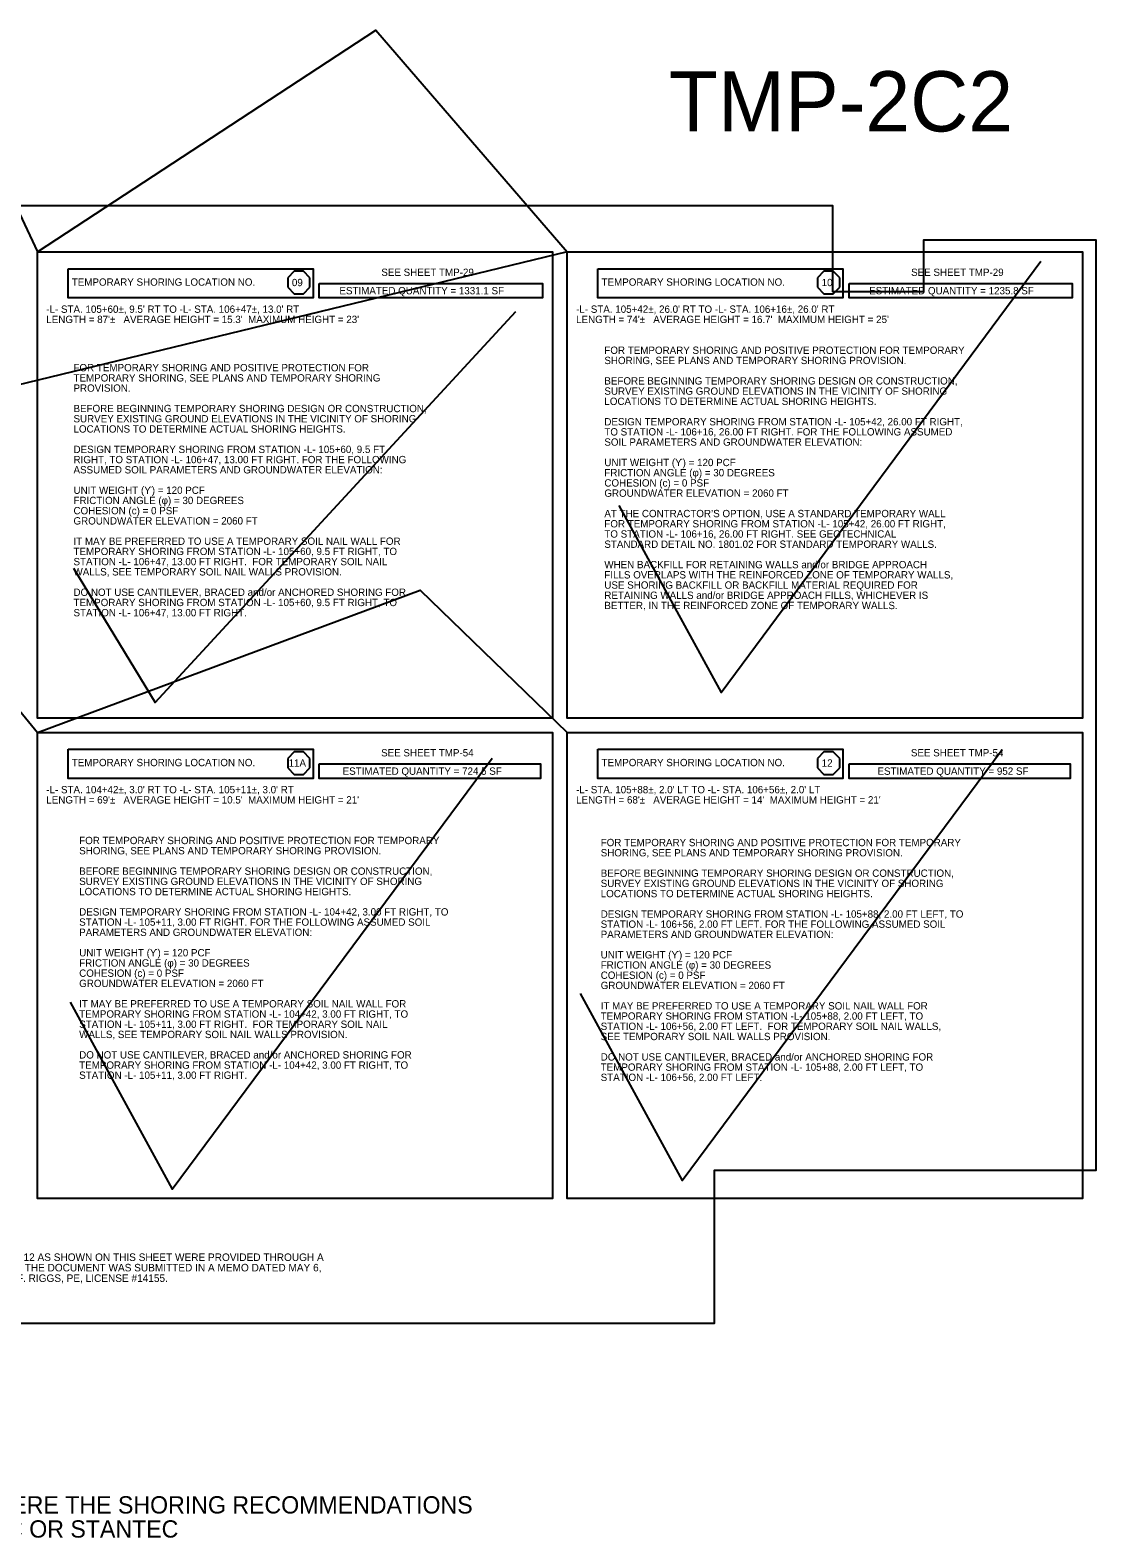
# Model space of a CAD drawing. Extents: x 2487012 to 2497594, y 369516 to 371986.
# Drawn here: x 2494835 to 2495826, y 370043 to 371445 of the extents above; entities that cross this region are included whole.
import ezdxf

# ---------------------------------------------------------------- set-up
doc = ezdxf.new("R2010")
doc.units = 0
for name, color, linetype in [('Scratch_Level_2', 7, 'Continuous'), ('Scratch_Level_6', 7, 'Continuous'), ('TC LABEL TEMP SHORING', 7, 'Continuous'), ('TC SHEET BORDER LINE THIN', 7, 'Continuous'), ('TC SHEET LAYOUT SHAPE', 7, 'Continuous'), ('TC SHEET TEXT', 7, 'Continuous')]:
    doc.layers.add(name, color=color, linetype=linetype)

msp = doc.modelspace()

# ---------------------------------------------------------------- linework, layer by layer
at = {"layer": 'Scratch_Level_2'}
for points in [[(2495382.7, 371003.4), (2495477.7, 370829.5), (2495775.3, 371230.4)], [(2494875.2, 370945), (2494951.2, 370819.9), (2495286.6, 371183.7)], [(2494872, 370541.3), (2494967, 370367.5), (2495264.6, 370768.3)], [(2495346.7, 370549.4), (2495441.6, 370375.6), (2495739.3, 370776.4)]]:
    msp.add_lwpolyline(points, dxfattribs=at)
at = {"layer": 'Scratch_Level_6'}
msp.add_lwpolyline([(2494336.4, 371282.3), (2494348.7, 371239.1), (2494750.3, 371433.4), (2494841.6, 371239.1), (2495156.4, 371445.4), (2495334.5, 371239.1), (2494163.1, 370955.2), (2494348.7, 370792.3), (2494709, 370953.9), (2494841.6, 370792.3), (2495197.6, 370924.6), (2495334.5, 370792.3)], dxfattribs=at)
at = {"layer": 'TC LABEL TEMP SHORING'}
for p, q in [((2495080.6, 371221.2), (2495074.5, 371215)), ((2495089.2, 371221.2), (2495080.6, 371221.2)), ((2495095.2, 371215), (2495089.2, 371221.2)), ((2495573.4, 371221.2), (2495567.4, 371215)), ((2495582.1, 371221.2), (2495573.4, 371221.2)), ((2495588.1, 371215), (2495582.1, 371221.2)), ((2495074.5, 371215), (2495074.5, 371206.3)), ((2495074.5, 371206.3), (2495080.6, 371200.1)), ((2495089.2, 371200.1), (2495095.2, 371206.3)), ((2495095.2, 371206.3), (2495095.2, 371215)), ((2495567.4, 371215), (2495567.4, 371206.3)), ((2495567.4, 371206.3), (2495573.4, 371200.1)), ((2495582.1, 371200.1), (2495588.1, 371206.3)), ((2495588.1, 371206.3), (2495588.1, 371215)), ((2495080.6, 371200.1), (2495089.2, 371200.1)), ((2495573.4, 371200.1), (2495582.1, 371200.1)), ((2495080.6, 370774.3), (2495074.5, 370768.1)), ((2495074.5, 370768.1), (2495074.5, 370759.4)), ((2495089.2, 370774.3), (2495080.6, 370774.3)), ((2495095.2, 370768.1), (2495089.2, 370774.3)), ((2495095.2, 370759.4), (2495095.2, 370768.1)), ((2495573.4, 370774.3), (2495567.4, 370768.1)), ((2495567.4, 370768.1), (2495567.4, 370759.4)), ((2495582.1, 370774.3), (2495573.4, 370774.3)), ((2495588.1, 370768.1), (2495582.1, 370774.3)), ((2495588.1, 370759.4), (2495588.1, 370768.1)), ((2495074.5, 370759.4), (2495080.6, 370753.2)), ((2495089.2, 370753.2), (2495095.2, 370759.4)), ((2495567.4, 370759.4), (2495573.4, 370753.2)), ((2495582.1, 370753.2), (2495588.1, 370759.4)), ((2495080.6, 370753.2), (2495089.2, 370753.2)), ((2495573.4, 370753.2), (2495582.1, 370753.2))]:
    msp.add_line(p, q, dxfattribs=at)
at = {"layer": 'TC SHEET BORDER LINE THIN'}
for points in [[(2494841.6, 371239.1), (2495321, 371239.1), (2495321, 370805.5), (2494841.6, 370805.5)], [(2495334.5, 371239.1), (2495813.9, 371239.1), (2495813.9, 370805.5), (2495334.5, 370805.5)], [(2494870.1, 371223.5), (2495098.1, 371223.5), (2495098.1, 371196.3), (2494870.1, 371196.3)], [(2495363, 371223.5), (2495591, 371223.5), (2495591, 371196.3), (2495363, 371196.3)], [(2495103.9, 371209.9), (2495311.4, 371209.9), (2495311.4, 371196.3), (2495103.9, 371196.3)], [(2495596.8, 371209.9), (2495804.3, 371209.9), (2495804.3, 371196.3), (2495596.8, 371196.3)], [(2494841.6, 370792.3), (2495321, 370792.3), (2495321, 370358.6), (2494841.6, 370358.6)], [(2495334.5, 370792.3), (2495813.9, 370792.3), (2495813.9, 370358.6), (2495334.5, 370358.6)], [(2494870.1, 370776.7), (2495098.1, 370776.7), (2495098.1, 370749.4), (2494870.1, 370749.4)], [(2495363, 370776.7), (2495591, 370776.7), (2495591, 370749.4), (2495363, 370749.4)], [(2495103.9, 370763), (2495309.7, 370763), (2495309.7, 370749.4), (2495103.9, 370749.4)], [(2495596.8, 370763), (2495802.6, 370763), (2495802.6, 370749.4), (2495596.8, 370749.4)]]:
    msp.add_lwpolyline(points, close=True, dxfattribs=at)
at = {"layer": 'TC SHEET LAYOUT SHAPE'}
msp.add_lwpolyline([(2494336.4, 370690.8), (2494336.4, 371000.2), (2494336.4, 371272.3), (2494346.4, 371282.3), (2494789.4, 371282.3), (2495260.4, 371282.3), (2495581.4, 371282.3), (2495581.4, 371202.3), (2495666.4, 371202.3), (2495666.4, 371250.3), (2495826.4, 371250.3), (2495826.4, 370915.3), (2495826.4, 370636.1), (2495826.4, 370384.8), (2495471.4, 370384.8), (2495471.4, 370242.3), (2495098.2, 370242.3), (2494928.7, 370242.3), (2494576, 370242.3), (2494336.4, 370242.3)], close=True, dxfattribs=at)

# ---------------------------------------------------------------- texts
at = {"layer": 'Scratch_Level_6'}
for s, p in [('MODIFY THIS DEPENDING ON WHERE THE SHORING RECOMMENDATIONS ', (2494464.6, 370065.7)), ('WERE SENT EITHER NCDOT WZTC OR STANTEC', (2494464.6, 370043.3))]:
    msp.add_text(s, height=16.094, dxfattribs=at).set_placement(p)
at = {"layer": 'TC LABEL TEMP SHORING'}
for s, p in [('09', (2495078.4, 371207.3)), ('10', (2495571.3, 371207.3)), ('11A', (2495075.3, 370760.4)), ('12', (2495571.3, 370760.4))]:
    msp.add_text(s, height=6.81, dxfattribs=at).set_placement(p)
at = {"layer": 'TC SHEET BORDER LINE THIN'}
for s, height, p in [('FOR TEMPORARY SHORING AND POSITIVE PROTECTION FOR TEMPORARY ', 6.814, (2495369.1, 371144.3)), ('FOR TEMPORARY SHORING AND POSITIVE PROTECTION FOR', 6.814, (2494875.2, 371128.1)), ('SHORING, SEE PLANS AND TEMPORARY SHORING PROVISION.', 6.814, (2495369.1, 371134.8)), ('TEMPORARY SHORING, SEE PLANS AND TEMPORARY SHORING', 6.814, (2494875.2, 371118.6)), ('BEFORE BEGINNING TEMPORARY SHORING DESIGN OR CONSTRUCTION, ', 6.814, (2495369.1, 371115.8)), ('PROVISION.', 6.81, (2494875.2, 371109.1)), ('SURVEY EXISTING GROUND ELEVATIONS IN THE VICINITY OF SHORING ', 6.814, (2495369.1, 371106.3)), ('BEFORE BEGINNING TEMPORARY SHORING DESIGN OR CONSTRUCTION,', 6.814, (2494875.2, 371090.1)), ('LOCATIONS TO DETERMINE ACTUAL SHORING HEIGHTS.', 6.814, (2495369.1, 371096.8)), ('SURVEY EXISTING GROUND ELEVATIONS IN THE VICINITY OF SHORING', 6.814, (2494875.2, 371080.6)), ('LOCATIONS TO DETERMINE ACTUAL SHORING HEIGHTS.', 6.814, (2494875.2, 371071.1)), ('DESIGN TEMPORARY SHORING FROM STATION -L- 105+42, 26.00 FT RIGHT, ', 6.814, (2495369.1, 371077.8)), ('TO STATION -L- 106+16, 26.00 FT RIGHT. FOR THE FOLLOWING ASSUMED ', 6.814, (2495369.1, 371068.4)), ('SOIL PARAMETERS AND GROUNDWATER ELEVATION:', 6.814, (2495369.1, 371058.9)), ('DESIGN TEMPORARY SHORING FROM STATION -L- 105+60, 9.5 FT', 6.814, (2494875.2, 371052.1)), ('RIGHT, TO STATION -L- 106+47, 13.00 FT RIGHT. FOR THE FOLLOWING', 6.814, (2494875.2, 371042.6)), ('ASSUMED SOIL PARAMETERS AND GROUNDWATER ELEVATION:', 6.814, (2494875.2, 371033.1)), ('UNIT WEIGHT (ϒ) = 120 PCF', 6.814, (2495369.1, 371039.9)), ('FRICTION ANGLE (φ) = 30 DEGREES', 6.814, (2495369.1, 371030.4)), ('UNIT WEIGHT (ϒ) = 120 PCF', 6.814, (2494875.2, 371014.1)), ('COHESION (c) = 0 PSF', 6.814, (2495369.1, 371020.9)), ('FRICTION ANGLE (φ) = 30 DEGREES', 6.814, (2494875.2, 371004.6)), ('GROUNDWATER ELEVATION = 2060 FT', 6.814, (2495369.1, 371011.4)), ('COHESION (c) = 0 PSF', 6.814, (2494875.2, 370995.1)), ('GROUNDWATER ELEVATION = 2060 FT', 6.814, (2494875.2, 370985.6)), ('AT THE CONTRACTOR’S OPTION, USE A STANDARD TEMPORARY WALL', 6.814, (2495369.1, 370992.4)), ('TO STATION -L- 106+16, 26.00 FT RIGHT. SEE GEOTECHNICAL', 6.814, (2495369.1, 370973.4)), ('FOR TEMPORARY SHORING FROM STATION -L- 105+42, 26.00 FT RIGHT,', 6.814, (2495369.1, 370982.9)), ('TEMPORARY SHORING FROM STATION -L- 105+60, 9.5 FT RIGHT, TO', 6.814, (2494875.2, 370957.2)), ('IT MAY BE PREFERRED TO USE A TEMPORARY SOIL NAIL WALL FOR', 6.814, (2494875.2, 370966.7)), ('STANDARD DETAIL NO. 1801.02 FOR STANDARD TEMPORARY WALLS.', 6.814, (2495369.1, 370963.9)), ('STATION -L- 106+47, 13.00 FT RIGHT.  FOR TEMPORARY SOIL NAIL', 6.814, (2494875.2, 370947.7)), ('WHEN BACKFILL FOR RETAINING WALLS and/or BRIDGE APPROACH', 6.814, (2495369.1, 370944.9)), ('WALLS, SEE TEMPORARY SOIL NAIL WALLS PROVISION.', 6.814, (2494875.2, 370938.2)), ('FILLS OVERLAPS WITH THE REINFORCED ZONE OF TEMPORARY WALLS,', 6.814, (2495369.1, 370935.4)), ('DO NOT USE CANTILEVER, BRACED and/or ANCHORED SHORING FOR', 6.814, (2494875.2, 370919.2)), ('USE SHORING BACKFILL OR BACKFILL MATERIAL REQUIRED FOR', 6.814, (2495369.1, 370925.9)), ('RETAINING WALLS and/or BRIDGE APPROACH FILLS, WHICHEVER IS', 6.814, (2495369.1, 370916.4)), ('TEMPORARY SHORING FROM STATION -L- 105+60, 9.5 FT RIGHT, TO', 6.814, (2494875.2, 370909.7)), ('BETTER, IN THE REINFORCED ZONE OF TEMPORARY WALLS.', 6.814, (2495369.1, 370906.9)), ('STATION -L- 106+47, 13.00 FT RIGHT.', 6.814, (2494875.2, 370900.2)), ('SHORING, SEE PLANS AND TEMPORARY SHORING PROVISION.', 6.814, (2494880.5, 370678.8)), ('FOR TEMPORARY SHORING AND POSITIVE PROTECTION FOR TEMPORARY ', 6.814, (2494880.5, 370688.3)), ('SHORING, SEE PLANS AND TEMPORARY SHORING PROVISION.', 6.814, (2495365.7, 370676.9)), ('FOR TEMPORARY SHORING AND POSITIVE PROTECTION FOR TEMPORARY ', 6.814, (2495365.7, 370686.4)), ('SURVEY EXISTING GROUND ELEVATIONS IN THE VICINITY OF SHORING ', 6.814, (2494880.5, 370650.3)), ('BEFORE BEGINNING TEMPORARY SHORING DESIGN OR CONSTRUCTION, ', 6.814, (2494880.5, 370659.8)), ('BEFORE BEGINNING TEMPORARY SHORING DESIGN OR CONSTRUCTION, ', 6.814, (2495365.7, 370657.9)), ('LOCATIONS TO DETERMINE ACTUAL SHORING HEIGHTS.', 6.814, (2494880.5, 370640.8)), ('SURVEY EXISTING GROUND ELEVATIONS IN THE VICINITY OF SHORING ', 6.814, (2495365.7, 370648.4)), ('LOCATIONS TO DETERMINE ACTUAL SHORING HEIGHTS.', 6.814, (2495365.7, 370638.9)), ('DESIGN TEMPORARY SHORING FROM STATION -L- 104+42, 3.00 FT RIGHT, TO ', 6.814, (2494880.5, 370621.9)), ('STATION -L- 105+11, 3.00 FT RIGHT. FOR THE FOLLOWING ASSUMED SOIL ', 6.814, (2494880.5, 370612.4)), ('STATION -L- 106+56, 2.00 FT LEFT. FOR THE FOLLOWING ASSUMED SOIL ', 6.814, (2495365.7, 370610.5)), ('DESIGN TEMPORARY SHORING FROM STATION -L- 105+88, 2.00 FT LEFT, TO ', 6.814, (2495365.7, 370619.9)), ('PARAMETERS AND GROUNDWATER ELEVATION:', 6.814, (2494880.5, 370602.9)), ('PARAMETERS AND GROUNDWATER ELEVATION:', 6.814, (2495365.7, 370601)), ('UNIT WEIGHT (ϒ) = 120 PCF', 6.814, (2494880.5, 370583.9)), ('UNIT WEIGHT (ϒ) = 120 PCF', 6.814, (2495365.7, 370582)), ('COHESION (c) = 0 PSF', 6.814, (2494880.5, 370564.9)), ('FRICTION ANGLE (φ) = 30 DEGREES', 6.814, (2494880.5, 370574.4)), ('FRICTION ANGLE (φ) = 30 DEGREES', 6.814, (2495365.7, 370572.5)), ('GROUNDWATER ELEVATION = 2060 FT', 6.814, (2494880.5, 370555.4)), ('COHESION (c) = 0 PSF', 6.814, (2495365.7, 370563)), ('GROUNDWATER ELEVATION = 2060 FT', 6.814, (2495365.7, 370553.5)), ('IT MAY BE PREFERRED TO USE A TEMPORARY SOIL NAIL WALL FOR', 6.814, (2494880.5, 370536.4)), ('TEMPORARY SHORING FROM STATION -L- 104+42, 3.00 FT RIGHT, TO', 6.814, (2494880.5, 370526.9)), ('TEMPORARY SHORING FROM STATION -L- 105+88, 2.00 FT LEFT, TO', 6.814, (2495365.7, 370525)), ('IT MAY BE PREFERRED TO USE A TEMPORARY SOIL NAIL WALL FOR', 6.814, (2495365.7, 370534.5)), ('STATION -L- 105+11, 3.00 FT RIGHT.  FOR TEMPORARY SOIL NAIL', 6.814, (2494880.5, 370517.4)), ('STATION -L- 106+56, 2.00 FT LEFT.  FOR TEMPORARY SOIL NAIL WALLS,', 6.814, (2495365.7, 370515.5)), ('WALLS, SEE TEMPORARY SOIL NAIL WALLS PROVISION.', 6.814, (2494880.5, 370507.9)), ('SEE TEMPORARY SOIL NAIL WALLS PROVISION.', 6.814, (2495365.7, 370506)), ('DO NOT USE CANTILEVER, BRACED and/or ANCHORED SHORING FOR', 6.814, (2494880.5, 370488.9)), ('DO NOT USE CANTILEVER, BRACED and/or ANCHORED SHORING FOR', 6.814, (2495365.7, 370487)), ('TEMPORARY SHORING FROM STATION -L- 104+42, 3.00 FT RIGHT, TO', 6.814, (2494880.5, 370479.4)), ('STATION -L- 105+11, 3.00 FT RIGHT.', 6.814, (2494880.5, 370470)), ('TEMPORARY SHORING FROM STATION -L- 105+88, 2.00 FT LEFT, TO', 6.814, (2495365.7, 370477.5)), ('STATION -L- 106+56, 2.00 FT LEFT.', 6.814, (2495365.7, 370468))]:
    msp.add_text(s, height=height, dxfattribs=at).set_placement(p)
at = {"layer": 'TC SHEET LAYOUT SHAPE'}
msp.add_text('TMP-2C2', height=56, rotation=0.0001, dxfattribs=at).set_placement((2495429, 371351.2))
at = {"layer": 'TC SHEET TEXT'}
for s, height, p in [('SEE SHEET TMP-29', 6.814, (2495161.6, 371216.8)), ('SEE SHEET TMP-29', 6.814, (2495654.5, 371216.8)), ('TEMPORARY SHORING LOCATION NO.', 6.814, (2494873.6, 371207.7)), ('ESTIMATED QUANTITY = 1331.1 SF', 6.814, (2495122.6, 371199.7)), ('TEMPORARY SHORING LOCATION NO.', 6.814, (2495366.5, 371207.7)), ('ESTIMATED QUANTITY = 1235.8 SF', 6.814, (2495615.5, 371199.7)), ("-L- STA. 105+60±, 9.5' RT TO -L- STA. 106+47±, 13.0' RT", 6.814, (2494849.9, 371182.5)), ("-L- STA. 105+42±, 26.0' RT TO -L- STA. 106+16±, 26.0' RT", 6.814, (2495342.8, 371182.5)), ("LENGTH = 87'±   AVERAGE HEIGHT = 15.3'  MAXIMUM HEIGHT = 23'", 6.814, (2494849.9, 371173)), ("LENGTH = 74'±   AVERAGE HEIGHT = 16.7'  MAXIMUM HEIGHT = 25'", 6.814, (2495342.8, 371173)), ('TEMPORARY SHORING LOCATION NO.', 6.814, (2494873.6, 370760.8)), ('SEE SHEET TMP-54', 6.814, (2495161.4, 370769.9)), ('TEMPORARY SHORING LOCATION NO.', 6.814, (2495366.5, 370760.8)), ('SEE SHEET TMP-54', 6.814, (2495654.3, 370769.9)), ('ESTIMATED QUANTITY = 724.5 SF', 6.814, (2495125.6, 370752.8)), ('ESTIMATED QUANTITY = 952 SF', 6.814, (2495623.2, 370752.8)), ("-L- STA. 104+42±, 3.0' RT TO -L- STA. 105+11±, 3.0' RT", 6.814, (2494849.9, 370735.6)), ("-L- STA. 105+88±, 2.0' LT TO -L- STA. 106+56±, 2.0' LT", 6.814, (2495342.8, 370735.6)), ("LENGTH = 69'±   AVERAGE HEIGHT = 10.5'  MAXIMUM HEIGHT = 21'", 6.814, (2494849.9, 370726.1)), ("LENGTH = 68'±   AVERAGE HEIGHT = 14'  MAXIMUM HEIGHT = 21'", 6.814, (2495342.8, 370726.1)), ('THE TEMPORARY SHORING NOTES FOR LOCATIONS 8 THRU 12 AS SHOWN ON THIS SHEET WERE PROVIDED THROUGH A ', 7, (2494548.9, 370300.6)), ('SEALED DOCUMENT FROM THE GEOTECHNICAL ENGINEER.  THE DOCUMENT WAS SUBMITTED IN A MEMO DATED MAY 6, ', 7, (2494548.9, 370290.9)), ('2026 AND SEALED BY A PROFESSIONAL ENGINEER, ABNER F. RIGGS, PE, LICENSE #14155.', 7, (2494548.9, 370281.1))]:
    msp.add_text(s, height=height, dxfattribs=at).set_placement(p)

doc.saveas('drawing.dxf')
